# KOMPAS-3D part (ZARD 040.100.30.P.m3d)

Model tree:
1. Плоскость XY
2. Плоскость ZX
3. Плоскость ZY
4. Ось X
5. Ось Y
6. Ось Z
7. Начало координат
8. Булева операция:1
9. Булева операция:2
10. Булева операция:3
11. Булева операция:4
12. Булева операция:5
13. Булева операция:6
